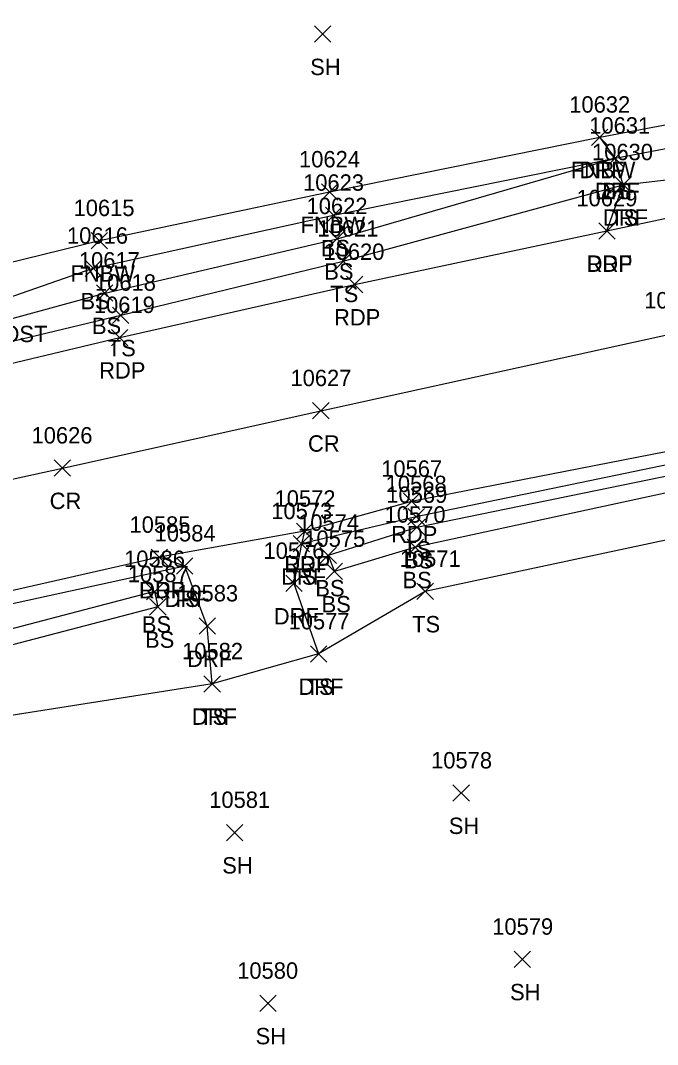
# Model space of a CAD drawing. Extents: x 1475671 to 1477951, y 592661 to 593821.
# Drawn here: x 1475754.2 to 1475831.9, y 592857.1 to 592982 of the extents above; entities that cross this region are included whole.
import ezdxf

# ---------------------------------------------------------------- set-up
doc = ezdxf.new("R2010")
doc.units = 0
for name, color, linetype in [('C_C', 7, 'Continuous'), ('L_A', 7, 'Continuous'), ('L_I', 7, 'Continuous'), ('L_TIC', 7, 'Continuous'), ('LELB', 7, 'Continuous'), ('LFNC', 7, 'Continuous'), ('P_A', 7, 'Continuous'), ('P_I', 7, 'Continuous'), ('P_TIC', 7, 'Continuous'), ('PET', 7, 'Continuous'), ('PRC', 7, 'Continuous'), ('R_A', 7, 'Continuous'), ('R_I', 7, 'Continuous'), ('R_TIC', 7, 'Continuous'), ('RDF', 7, 'Continuous')]:
    doc.layers.add(name, color=color, linetype=linetype)

msp = doc.modelspace()

# ---------------------------------------------------------------- linework, layer by layer
at = {"layer": 'L_TIC'}
for points in [[(1475790.07, 592979.34), (1475792.07, 592981.34)], [(1475792.07, 592979.34), (1475790.07, 592981.34)], [(1475823.89, 592966.76), (1475825.89, 592968.76)], [(1475825.89, 592966.76), (1475823.89, 592968.76)], [(1475825.76, 592964.2), (1475827.76, 592966.2)], [(1475827.76, 592964.2), (1475825.76, 592966.2)], [(1475825.76, 592964.2), (1475827.76, 592966.2)], [(1475827.76, 592964.2), (1475825.76, 592966.2)], [(1475826.75, 592960.96), (1475828.75, 592962.96)], [(1475828.75, 592960.96), (1475826.75, 592962.96)], [(1475790.92, 592960.08), (1475792.92, 592962.08)], [(1475792.92, 592960.08), (1475790.92, 592962.08)], [(1475791.41, 592957.23), (1475793.41, 592959.23)], [(1475793.41, 592957.23), (1475791.41, 592959.23)], [(1475762.84, 592954.14), (1475764.84, 592956.14)], [(1475764.84, 592954.14), (1475762.84, 592956.14)], [(1475791.84, 592954.38), (1475793.84, 592956.38)], [(1475793.84, 592954.38), (1475791.84, 592956.38)], [(1475792.6, 592951.64), (1475794.6, 592953.64)], [(1475794.6, 592951.64), (1475792.6, 592953.64)], [(1475762.09, 592950.77), (1475764.09, 592952.77)], [(1475764.09, 592950.77), (1475762.09, 592952.77)], [(1475763.49, 592947.74), (1475765.49, 592949.74)], [(1475765.49, 592947.74), (1475763.49, 592949.74)], [(1475765.45, 592945.03), (1475767.45, 592947.03)], [(1475767.45, 592945.03), (1475765.45, 592947.03)], [(1475801.49, 592920.46), (1475803.49, 592922.46)], [(1475803.49, 592920.46), (1475801.49, 592922.46)], [(1475801.57, 592919.15), (1475803.57, 592921.15)], [(1475803.57, 592919.15), (1475801.57, 592921.15)], [(1475787.48, 592917.16), (1475789.48, 592919.16)], [(1475789.48, 592917.16), (1475787.48, 592919.16)], [(1475801.39, 592916.73), (1475803.39, 592918.73)], [(1475803.39, 592916.73), (1475801.39, 592918.73)], [(1475790.75, 592915.74), (1475792.75, 592917.74)], [(1475792.75, 592915.74), (1475790.75, 592917.74)], [(1475773.25, 592914.44), (1475775.25, 592916.44)], [(1475775.25, 592914.44), (1475773.25, 592916.44)], [(1475791.51, 592913.78), (1475793.51, 592915.78)], [(1475793.51, 592913.78), (1475791.51, 592915.78)], [(1475791.51, 592913.78), (1475793.51, 592915.78)], [(1475793.51, 592913.78), (1475791.51, 592915.78)], [(1475769.57, 592911.32), (1475771.57, 592913.32)], [(1475771.57, 592911.32), (1475769.57, 592913.32)], [(1475769.57, 592911.32), (1475771.57, 592913.32)], [(1475771.57, 592911.32), (1475769.57, 592913.32)], [(1475802.59, 592911.34), (1475804.59, 592913.34)], [(1475804.59, 592911.34), (1475802.59, 592913.34)], [(1475769.97, 592909.46), (1475771.97, 592911.46)], [(1475771.97, 592909.46), (1475769.97, 592911.46)], [(1475789.59, 592903.71), (1475791.59, 592905.71)], [(1475791.59, 592903.71), (1475789.59, 592905.71)], [(1475776.6, 592900.06), (1475778.6, 592902.06)], [(1475778.6, 592900.06), (1475776.6, 592902.06)], [(1475806.98, 592886.74), (1475808.98, 592888.74)], [(1475808.98, 592886.74), (1475806.98, 592888.74)], [(1475779.34, 592881.92), (1475781.34, 592883.92)], [(1475781.34, 592881.92), (1475779.34, 592883.92)], [(1475814.45, 592866.45), (1475816.45, 592868.45)], [(1475816.45, 592866.45), (1475814.45, 592868.45)], [(1475783.41, 592861.08), (1475785.41, 592863.08)], [(1475785.41, 592861.08), (1475783.41, 592863.08)]]:
    msp.add_lwpolyline(points, dxfattribs=at)
at = {"layer": 'LELB'}
for points in [[(1475681.97, 592926.29), (1475693.99, 592930.92), (1475717.71, 592935.95), (1475764.49, 592948.74), (1475792.84, 592955.38), (1475826.76, 592965.2), (1475839.14, 592967.57), (1475847.44, 592968.45), (1475896, 592975.83), (1475948.75, 592985.5), (1475992.67, 592993.57), (1476057.44, 593003.96), (1476113.1, 593013.57), (1476163.64, 593021.28), (1476215.98, 593029.82), (1476272.69, 593037.85), (1476322.72, 593046.24), (1476372.45, 593058.02), (1476374.59, 593060.62), (1476398.56, 593065.83), (1476415.47, 593071.31), (1476457.34, 593084.84)], [(1475681.68, 592929.89), (1475693.99, 592930.92), (1475717.95, 592934.41), (1475766.45, 592946.03), (1475793.6, 592952.64), (1475827.75, 592961.96), (1475839.66, 592963.32), (1475897.61, 592972.89), (1475949.51, 592982.21), (1475996.32, 592990.67), (1476057.58, 593001.03), (1476113.5, 593010.46), (1476164.33, 593018.66), (1476216.45, 593027.16), (1476273.17, 593035.57), (1476322.97, 593043.9), (1476372.64, 593054.79), (1476374.63, 593058.12)], [(1476521.14, 593041.18), (1476464.22, 593030.64), (1476420.77, 593020.64), (1476368.55, 593014.29), (1476359.82, 593012.38), (1476319.88, 593006.6), (1476267.05, 592998.99), (1476216.33, 592991.85), (1476164.01, 592984.31), (1476119.67, 592976.43), (1476101.12, 592973.12), (1476050.25, 592964.51), (1475994.64, 592956.24), (1475948.73, 592947.98), (1475899.49, 592939.5), (1475855.9, 592931.1), (1475802.57, 592920.15), (1475791.75, 592916.74), (1475792.51, 592914.78)], [(1476534.65, 593028.56), (1476525.69, 593019.5), (1476511.54, 593017.85), (1476467.31, 593015.01), (1476422.73, 593008.46), (1476366.85, 593001.28), (1476356.63, 592997.77), (1476347.04, 593000.45), (1476320.8, 592997.35), (1476267.98, 592990.13), (1476216.9, 592984.46), (1476165.76, 592976.73), (1476117.9, 592968.73), (1476100.74, 592966.91), (1476051.72, 592958.25), (1475996.01, 592950.36), (1475948.39, 592939), (1475900.82, 592931.75), (1475857.92, 592923.91), (1475803.59, 592912.34), (1475790.59, 592904.71)], [(1476511.04, 593028.14), (1476465.56, 593023.07), (1476421.22, 593014.7), (1476366.44, 593009.67), (1476355.54, 593008.55), (1476320.37, 593003.18), (1476267.54, 592995.9), (1476216.93, 592987.92), (1476164.84, 592980.53), (1476118, 592971.7), (1476100.88, 592970.48), (1476050.95, 592961.21), (1475995.34, 592954.17), (1475949.24, 592944.73), (1475901.01, 592937.79), (1475856.17, 592929.37), (1475802.39, 592917.73), (1475792.51, 592914.78)], [(1476119.67, 592976.43), (1476100.91, 592975.21), (1476049.54, 592966.45), (1475994.72, 592957.82), (1475948.15, 592950.07), (1475899.13, 592941.1), (1475855.65, 592932.47), (1475802.49, 592921.46), (1475788.48, 592918.16)], [(1475717.71, 592935.95), (1475763.09, 592951.77), (1475792.41, 592958.23), (1475826.76, 592965.2)], [(1475774.25, 592915.44), (1475722.89, 592904.21), (1475686.82, 592894.57)], [(1475770.57, 592912.32), (1475722.85, 592899.83), (1475686.91, 592887.85)], [(1475770.57, 592912.32), (1475770.97, 592910.46), (1475723.2, 592897.97), (1475686.93, 592883.52)], [(1475777.6, 592901.06), (1475726.42, 592893.01), (1475687.86, 592878.74)]]:
    msp.add_lwpolyline(points, dxfattribs=at)
at = {"layer": 'LFNC'}
msp.add_lwpolyline([(1475680.63, 592937.28), (1475715.61, 592943.34), (1475763.84, 592955.14), (1475791.92, 592961.08), (1475824.89, 592967.76), (1475839.13, 592970.46), (1475847.47, 592971.97), (1475895.02, 592980.45), (1475948.31, 592989.25), (1475993.78, 592996.67), (1476056.99, 593006.94), (1476113.81, 593016.03), (1476164.23, 593025.08), (1476215.07, 593032.59), (1476272.43, 593042.08), (1476322.23, 593049.67), (1476368.09, 593057.49), (1476372.45, 593058.02), (1476374.63, 593058.12), (1476399.83, 593064.01), (1476415.89, 593069.22), (1476458.99, 593083.01), (1476499.73, 593099.84)], dxfattribs=at)
at = {"layer": 'P_TIC'}
for points in [[(1475824.77, 592955.33), (1475826.77, 592957.33)], [(1475826.77, 592955.33), (1475824.77, 592957.33)], [(1475793.98, 592948.79), (1475795.98, 592950.79)], [(1475795.98, 592948.79), (1475793.98, 592950.79)], [(1475765.32, 592942.31), (1475767.32, 592944.31)], [(1475767.32, 592942.31), (1475765.32, 592944.31)], [(1475789.86, 592933.39), (1475791.86, 592935.39)], [(1475791.86, 592933.39), (1475789.86, 592935.39)], [(1475758.33, 592926.39), (1475760.33, 592928.39)], [(1475760.33, 592926.39), (1475758.33, 592928.39)], [(1475800.94, 592922.33), (1475802.94, 592924.33)], [(1475802.94, 592922.33), (1475800.94, 592924.33)], [(1475787.88, 592918.68), (1475789.88, 592920.68)], [(1475789.88, 592918.68), (1475787.88, 592920.68)], [(1475770.17, 592915.5), (1475772.17, 592917.5)], [(1475772.17, 592915.5), (1475770.17, 592917.5)]]:
    msp.add_lwpolyline(points, dxfattribs=at)
at = {"layer": 'PET'}
for points in [[(1475682.06, 592924.71), (1475717.58, 592931.68), (1475766.32, 592943.31), (1475794.98, 592949.79), (1475825.77, 592956.33), (1475844.1, 592960.26), (1475899.54, 592970.95), (1475949.72, 592980.21), (1475996.45, 592988.43), (1476057.84, 592998.4), (1476110.05, 593006.96), (1476164.18, 593015.73), (1476216.75, 593023.76), (1476273.83, 593032.32), (1476323.32, 593041.42), (1476373.65, 593052.29), (1476409.24, 593061.35), (1476416.16, 593063.9), (1476459.25, 593078.48), (1476508.39, 593100.17)], [(1476521.33, 593044.37), (1476462.5, 593038.2), (1476408.69, 593032.05), (1476367.34, 593022.2), (1476318.64, 593012.07), (1476266.69, 593003.36), (1476216.58, 592995.35), (1476163.86, 592987.33), (1476119.65, 592980.05), (1476101.05, 592977.22), (1476048.95, 592968.83), (1475997.04, 592960.32), (1475947.8, 592951.63), (1475898.72, 592942.8), (1475855.26, 592933.74), (1475801.94, 592923.33), (1475788.88, 592919.68), (1475771.17, 592916.5), (1475722.69, 592905.51), (1475685.82, 592897.63)]]:
    msp.add_lwpolyline(points, dxfattribs=at)
at = {"layer": 'PRC'}
msp.add_lwpolyline([(1475683.62, 592911.01), (1475719.65, 592918.7), (1475759.33, 592927.39), (1475790.86, 592934.39), (1475834.03, 592943.87), (1475901.67, 592957.18), (1475953.57, 592967.02), (1476000.12, 592975.16), (1476059.54, 592984.65), (1476113.3, 592993.58), (1476166.39, 593001.74), (1476218.93, 593009.6), (1476277, 593018.86), (1476325.59, 593027.6), (1476377.06, 593038.84), (1476415.44, 593049.14), (1476421.8, 593050.95), (1476461.98, 593064.62), (1476520.7, 593090.52)], dxfattribs=at)
at = {"layer": 'R_TIC'}
for points in [[(1475823.89, 592966.76), (1475825.89, 592968.76)], [(1475825.89, 592966.76), (1475823.89, 592968.76)], [(1475825.76, 592964.2), (1475827.76, 592966.2)], [(1475827.76, 592964.2), (1475825.76, 592966.2)], [(1475826.75, 592960.96), (1475828.75, 592962.96)], [(1475828.75, 592960.96), (1475826.75, 592962.96)], [(1475824.77, 592955.33), (1475826.77, 592957.33)], [(1475826.77, 592955.33), (1475824.77, 592957.33)], [(1475787.88, 592918.68), (1475789.88, 592920.68)], [(1475789.88, 592918.68), (1475787.88, 592920.68)], [(1475787.48, 592917.16), (1475789.48, 592919.16)], [(1475789.48, 592917.16), (1475787.48, 592919.16)], [(1475770.17, 592915.5), (1475772.17, 592917.5)], [(1475772.17, 592915.5), (1475770.17, 592917.5)], [(1475773.25, 592914.44), (1475775.25, 592916.44)], [(1475775.25, 592914.44), (1475773.25, 592916.44)], [(1475786.58, 592912.31), (1475788.58, 592914.31)], [(1475788.58, 592912.31), (1475786.58, 592914.31)], [(1475776, 592907.12), (1475778, 592909.12)], [(1475778, 592907.12), (1475776, 592909.12)], [(1475789.59, 592903.71), (1475791.59, 592905.71)], [(1475791.59, 592903.71), (1475789.59, 592905.71)], [(1475776.6, 592900.06), (1475778.6, 592902.06)], [(1475778.6, 592900.06), (1475776.6, 592902.06)]]:
    msp.add_lwpolyline(points, dxfattribs=at)
at = {"layer": 'RDF'}
for points in [[(1475825.77, 592956.33), (1475827.75, 592961.96), (1475826.76, 592965.2), (1475824.89, 592967.76)], [(1475788.88, 592919.68), (1475788.48, 592918.16), (1475787.58, 592913.31), (1475790.59, 592904.71), (1475777.6, 592901.06), (1475777, 592908.12), (1475774.25, 592915.44), (1475771.17, 592916.5)]]:
    msp.add_lwpolyline(points, dxfattribs=at)

# ---------------------------------------------------------------- texts
at = {"layer": 'C_C'}
msp.add_text('TIE=23.70 FN POST', height=2, dxfattribs=at).set_placement((1475732.75, 592942.76))
at = {"layer": 'L_A'}
for s, p in [('SH', (1475789.56, 592975.34)), ('FNBW', (1475821.36, 592962.76)), ('BS', (1475825.2, 592960.2)), ('BS', (1475825.2, 592960.2)), ('FNBW', (1475788.39, 592956.08)), ('TS', (1475826.16, 592956.96)), ('BS', (1475790.85, 592953.23)), ('FNBW', (1475760.31, 592950.14)), ('BS', (1475791.28, 592950.38)), ('TS', (1475792.01, 592947.64)), ('BS', (1475761.53, 592946.77)), ('BS', (1475762.93, 592943.74)), ('TS', (1475764.86, 592941.03)), ('TS', (1475800.9, 592916.46)), ('BS', (1475801.01, 592915.15)), ('TS', (1475786.89, 592913.16)), ('BS', (1475800.83, 592912.73)), ('BS', (1475790.19, 592911.74)), ('TS', (1475772.66, 592910.44)), ('BS', (1475790.95, 592909.78)), ('BS', (1475790.95, 592909.78)), ('BS', (1475769.02, 592907.32)), ('BS', (1475769.02, 592907.32)), ('TS', (1475802, 592907.34)), ('BS', (1475769.41, 592905.46)), ('TS', (1475789, 592899.71)), ('TS', (1475776.01, 592896.06)), ('SH', (1475806.47, 592882.74)), ('SH', (1475778.83, 592877.92)), ('SH', (1475813.94, 592862.45)), ('SH', (1475782.9, 592857.08))]:
    msp.add_text(s, height=2, dxfattribs=at).set_placement(p)
at = {"layer": 'L_I'}
for s, p in [('10632', (1475821.17, 592970.76)), ('10631', (1475823.61, 592968.2)), ('10631', (1475823.61, 592968.2)), ('10630', (1475823.95, 592964.96)), ('10624', (1475788.2, 592964.08)), ('10623', (1475788.69, 592961.23)), ('10615', (1475760.69, 592958.14)), ('10622', (1475789.12, 592958.38)), ('10616', (1475759.89, 592954.77)), ('10621', (1475790.45, 592955.64)), ('10617', (1475761.34, 592951.74)), ('10618', (1475763.3, 592949.03)), ('10568', (1475798.77, 592924.46)), ('10569', (1475798.85, 592923.15)), ('10573', (1475784.81, 592921.16)), ('10574', (1475788.08, 592919.74)), ('10570', (1475798.64, 592920.73)), ('10584', (1475770.58, 592918.44)), ('10575', (1475788.84, 592917.78)), ('10575', (1475788.84, 592917.78)), ('10586', (1475766.85, 592915.32)), ('10586', (1475766.85, 592915.32)), ('10571', (1475800.49, 592915.34)), ('10587', (1475767.3, 592913.46)), ('10577', (1475786.92, 592907.71)), ('10582', (1475773.93, 592904.06)), ('10578', (1475804.31, 592890.74)), ('10581', (1475777.24, 592885.92)), ('10579', (1475811.77, 592870.45)), ('10580', (1475780.65, 592865.08))]:
    msp.add_text(s, height=2, dxfattribs=at).set_placement(p)
at = {"layer": 'P_A'}
for s, p in [('RDP', (1475823.26, 592951.33)), ('RDP', (1475792.47, 592944.79)), ('RDP', (1475763.81, 592938.31)), ('CR', (1475789.29, 592929.39)), ('CR', (1475757.77, 592922.39)), ('RDP', (1475799.43, 592918.33)), ('RDP', (1475786.37, 592914.68)), ('RDP', (1475768.66, 592911.5))]:
    msp.add_text(s, height=2, dxfattribs=at).set_placement(p)
at = {"layer": 'P_I'}
for s, p in [('10629', (1475822.04, 592959.33)), ('10620', (1475791.18, 592952.79)), ('10619', (1475763.17, 592946.31)), ('10628', (1475830.31, 592946.87)), ('10627', (1475787.15, 592937.39)), ('10626', (1475755.56, 592930.39)), ('10567', (1475798.22, 592926.33)), ('10572', (1475785.21, 592922.68)), ('10585', (1475767.51, 592919.5))]:
    msp.add_text(s, height=2, dxfattribs=at).set_placement(p)
at = {"layer": 'R_A'}
for p in [(1475822.43, 592962.76), (1475824.3, 592960.2), (1475825.28, 592956.96), (1475823.3, 592951.33), (1475786.41, 592914.68), (1475786.01, 592913.16), (1475768.71, 592911.5), (1475771.79, 592910.44), (1475785.12, 592908.31), (1475774.54, 592903.12), (1475788.13, 592899.71), (1475775.13, 592896.06)]:
    msp.add_text('DRF', height=2, dxfattribs=at).set_placement(p)
at = {"layer": 'R_I'}
for s, p in [('10632', (1475821.17, 592970.76)), ('10631', (1475823.61, 592968.2)), ('10630', (1475823.95, 592964.96)), ('10629', (1475822.04, 592959.33)), ('10572', (1475785.21, 592922.68)), ('10573', (1475784.81, 592921.16)), ('10585', (1475767.51, 592919.5)), ('10584', (1475770.58, 592918.44)), ('10576', (1475783.86, 592916.31)), ('10583', (1475773.33, 592911.12)), ('10577', (1475786.92, 592907.71)), ('10582', (1475773.93, 592904.06))]:
    msp.add_text(s, height=2, dxfattribs=at).set_placement(p)

doc.saveas('drawing.dxf')
